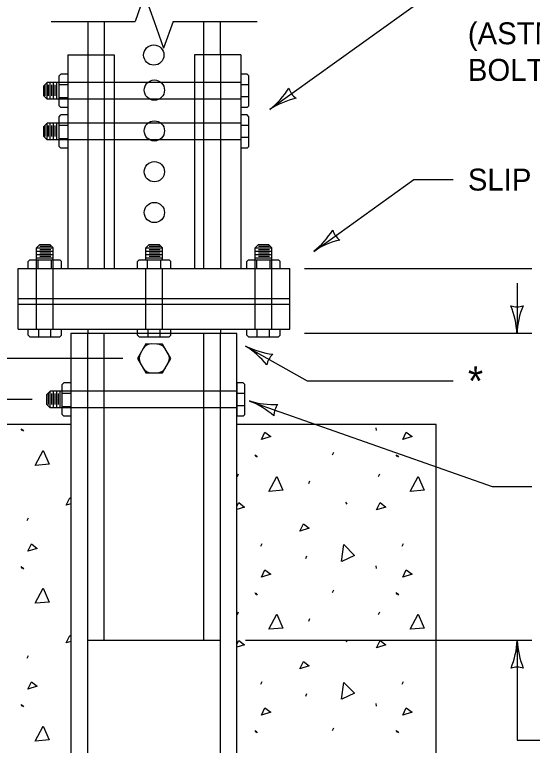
# Model space of a CAD drawing. Extents: x 49940 to 50043, y 49986 to 50011.
# Drawn here: x 50027.696 to 50029.113, y 49992.517 to 49994.515 of the extents above; entities that cross this region are included whole.
import ezdxf

# ---------------------------------------------------------------- set-up
doc = ezdxf.new("R2010")
doc.units = 0
for name, color, linetype in [('Level 1', 7, 'Continuous'), ('Level 2', 7, 'Continuous'), ('Level 3', 7, 'Continuous'), ('Level 4', 7, 'Continuous'), ('Level 6', 7, 'Continuous')]:
    doc.layers.add(name, color=color, linetype=linetype)

msp = doc.modelspace()

# ---------------------------------------------------------------- linework, layer by layer
at = {"layer": 'Level 1'}
for p, q in [((50027.8417, 49994.4053), (50027.8417, 49993.8208)), ((50027.8417, 49994.4053), (50027.9689, 49994.4053)), ((50027.9689, 49994.4053), (50027.9689, 49993.8208)), ((50028.1884, 49994.4053), (50028.1884, 49993.8208)), ((50028.3156, 49994.4053), (50028.1884, 49994.4053)), ((50028.3156, 49994.4053), (50028.3156, 49993.8208)), ((50027.8181, 49994.3475), (50027.8226, 49994.352)), ((50027.8181, 49994.2656), (50027.8181, 49994.3475)), ((50027.8417, 49994.352), (50027.8226, 49994.352)), ((50028.3323, 49994.352), (50028.3156, 49994.352)), ((50028.3368, 49994.3475), (50028.3323, 49994.352)), ((50028.3368, 49994.2656), (50028.3368, 49994.3475)), ((50027.7758, 49994.3202), (50027.7849, 49994.3293)), ((50027.8181, 49994.3293), (50027.7849, 49994.3293)), ((50027.7849, 49994.2839), (50027.7849, 49994.3293)), ((50027.7939, 49994.2839), (50027.7939, 49994.3293)), ((50027.8031, 49994.2839), (50027.8031, 49994.3293)), ((50027.8121, 49994.2839), (50027.8121, 49994.3293)), ((50027.7758, 49994.2931), (50027.7758, 49994.3202)), ((50027.7803, 49994.2932), (50027.7803, 49994.323)), ((50027.7894, 49994.2932), (50027.7894, 49994.323)), ((50027.7985, 49994.2932), (50027.7985, 49994.323)), ((50027.8076, 49994.2932), (50027.8076, 49994.323)), ((50027.8181, 49994.3241), (50027.8405, 49994.3241)), ((50028.3368, 49994.323), (50028.3162, 49994.323)), ((50027.7758, 49994.2931), (50027.7849, 49994.2839)), ((50027.8181, 49994.2879), (50027.8405, 49994.2879)), ((50028.3368, 49994.29), (50028.3162, 49994.29)), ((50027.8181, 49994.2839), (50027.7849, 49994.2839)), ((50027.8181, 49994.2656), (50027.8226, 49994.2612)), ((50027.8417, 49994.2612), (50027.8226, 49994.2612)), ((50028.3323, 49994.2612), (50028.3156, 49994.2612)), ((50028.3323, 49994.2612), (50028.3368, 49994.2656)), ((50027.8181, 49994.2359), (50027.8226, 49994.2405)), ((50027.8181, 49994.1541), (50027.8181, 49994.2359)), ((50027.8417, 49994.2405), (50027.8226, 49994.2405)), ((50028.3323, 49994.2405), (50028.3156, 49994.2405)), ((50028.3368, 49994.2359), (50028.3323, 49994.2405)), ((50028.3368, 49994.1541), (50028.3368, 49994.2359)), ((50027.7758, 49994.2087), (50027.7849, 49994.2178)), ((50027.7758, 49994.1816), (50027.7758, 49994.2087)), ((50027.7803, 49994.1816), (50027.7803, 49994.2115)), ((50027.8181, 49994.2178), (50027.7849, 49994.2178)), ((50027.7849, 49994.1723), (50027.7849, 49994.2178)), ((50027.7894, 49994.1816), (50027.7894, 49994.2115)), ((50027.7939, 49994.1723), (50027.7939, 49994.2178)), ((50027.7985, 49994.1816), (50027.7985, 49994.2115)), ((50027.8031, 49994.1723), (50027.8031, 49994.2178)), ((50027.8076, 49994.1816), (50027.8076, 49994.2115)), ((50027.8121, 49994.1723), (50027.8121, 49994.2178)), ((50027.8181, 49994.2126), (50027.8405, 49994.2126)), ((50028.3368, 49994.2115), (50028.3162, 49994.2115)), ((50027.7758, 49994.1816), (50027.7849, 49994.1723)), ((50027.8181, 49994.1723), (50027.7849, 49994.1723)), ((50027.8181, 49994.1763), (50027.8405, 49994.1763)), ((50028.3368, 49994.1785), (50028.3162, 49994.1785)), ((50027.8181, 49994.1541), (50027.8226, 49994.1496)), ((50027.8417, 49994.1496), (50027.8226, 49994.1496)), ((50028.3323, 49994.1496), (50028.3156, 49994.1496)), ((50028.3323, 49994.1496), (50028.3368, 49994.1541)), ((50027.7653, 49993.8865), (50027.7562, 49993.8775)), ((50027.7562, 49993.8443), (50027.7562, 49993.8775)), ((50027.7562, 49993.8775), (50027.8016, 49993.8775)), ((50027.7562, 49993.8685), (50027.8016, 49993.8685)), ((50027.7653, 49993.8865), (50027.7925, 49993.8865)), ((50027.7654, 49993.8821), (50027.7953, 49993.8821)), ((50027.7654, 49993.873), (50027.7953, 49993.873)), ((50027.7925, 49993.8865), (50027.8016, 49993.8775)), ((50027.8016, 49993.8443), (50027.8016, 49993.8775)), ((50028.0643, 49993.8865), (50028.0552, 49993.8775)), ((50028.0552, 49993.8443), (50028.0552, 49993.8775)), ((50028.0552, 49993.8775), (50028.1007, 49993.8775)), ((50028.0552, 49993.8685), (50028.1007, 49993.8685)), ((50028.0643, 49993.8865), (50028.0916, 49993.8865)), ((50028.0645, 49993.8821), (50028.0944, 49993.8821)), ((50028.0645, 49993.873), (50028.0944, 49993.873)), ((50028.0916, 49993.8865), (50028.1007, 49993.8775)), ((50028.1007, 49993.8443), (50028.1007, 49993.8775)), ((50028.3634, 49993.8865), (50028.3543, 49993.8775)), ((50028.3543, 49993.8443), (50028.3543, 49993.8775)), ((50028.3543, 49993.8775), (50028.3997, 49993.8775)), ((50028.3543, 49993.8685), (50028.3997, 49993.8685)), ((50028.3634, 49993.8865), (50028.3906, 49993.8865)), ((50028.3635, 49993.8821), (50028.3934, 49993.8821)), ((50028.3635, 49993.873), (50028.3934, 49993.873)), ((50028.3906, 49993.8865), (50028.3997, 49993.8775)), ((50028.3997, 49993.8443), (50028.3997, 49993.8775)), ((50027.7562, 49993.8593), (50027.8016, 49993.8593)), ((50027.7562, 49993.8503), (50027.8016, 49993.8503)), ((50027.7654, 49993.8639), (50027.7953, 49993.8639)), ((50027.7654, 49993.8548), (50027.7953, 49993.8548)), ((50028.0552, 49993.8593), (50028.1007, 49993.8593)), ((50028.0552, 49993.8503), (50028.1007, 49993.8503)), ((50028.0645, 49993.8639), (50028.0944, 49993.8639)), ((50028.0645, 49993.8548), (50028.0944, 49993.8548)), ((50028.3543, 49993.8593), (50028.3997, 49993.8593)), ((50028.3543, 49993.8503), (50028.3997, 49993.8503)), ((50028.3635, 49993.8639), (50028.3934, 49993.8639)), ((50028.3635, 49993.8548), (50028.3934, 49993.8548)), ((50027.7379, 49993.8443), (50027.7335, 49993.8397)), ((50027.7335, 49993.8208), (50027.7335, 49993.8397)), ((50027.7379, 49993.8443), (50027.8198, 49993.8443)), ((50027.7601, 49993.8443), (50027.7601, 49993.8219)), ((50027.7963, 49993.8443), (50027.7963, 49993.8219)), ((50027.8198, 49993.8443), (50027.8244, 49993.8397)), ((50027.8244, 49993.8208), (50027.8244, 49993.8397)), ((50028.037, 49993.8443), (50028.0324, 49993.8397)), ((50028.0324, 49993.8208), (50028.0324, 49993.8397)), ((50028.037, 49993.8443), (50028.1188, 49993.8443)), ((50028.0593, 49993.8443), (50028.0593, 49993.8219)), ((50028.0953, 49993.8443), (50028.0953, 49993.8219)), ((50028.1188, 49993.8443), (50028.1233, 49993.8397)), ((50028.1233, 49993.8208), (50028.1233, 49993.8397)), ((50028.3361, 49993.8443), (50028.3315, 49993.8397)), ((50028.3315, 49993.8208), (50028.3315, 49993.8397)), ((50028.3361, 49993.8443), (50028.4179, 49993.8443)), ((50028.3582, 49993.8443), (50028.3582, 49993.8219)), ((50028.3944, 49993.8443), (50028.3944, 49993.8219)), ((50028.4179, 49993.8443), (50028.4224, 49993.8397)), ((50028.4224, 49993.8208), (50028.4224, 49993.8397)), ((50027.7062, 49993.6548), (50027.7062, 49993.8208)), ((50027.7062, 49993.8208), (50028.0552, 49993.8208)), ((50028.0552, 49993.6548), (50028.0552, 49993.8208)), ((50028.0552, 49993.8208), (50028.1007, 49993.8208)), ((50028.1007, 49993.6548), (50028.1007, 49993.8208)), ((50028.1007, 49993.8208), (50028.4497, 49993.8208)), ((50028.4497, 49993.6548), (50028.4497, 49993.8208)), ((50027.7062, 49993.7383), (50028.4497, 49993.7383)), ((50027.7062, 49993.7234), (50028.4497, 49993.7234)), ((50027.7062, 49993.6548), (50028.0552, 49993.6548)), ((50027.7335, 49993.6381), (50027.7335, 49993.6548)), ((50027.7622, 49993.6337), (50027.7622, 49993.6543)), ((50027.7953, 49993.6337), (50027.7953, 49993.6543)), ((50027.8244, 49993.6381), (50027.8244, 49993.6548)), ((50027.8963, 49993.6548), (50027.8963, 49993.6425)), ((50028.0324, 49993.6381), (50028.0324, 49993.6548)), ((50028.0552, 49993.6548), (50028.1007, 49993.6548)), ((50028.0613, 49993.6337), (50028.0613, 49993.6543)), ((50028.0944, 49993.6337), (50028.0944, 49993.6543)), ((50028.1007, 49993.6548), (50028.4497, 49993.6548)), ((50028.1233, 49993.6381), (50028.1233, 49993.6548)), ((50028.2596, 49993.6548), (50028.2596, 49993.6425)), ((50028.3315, 49993.6381), (50028.3315, 49993.6548)), ((50028.3603, 49993.6337), (50028.3603, 49993.6543)), ((50028.3934, 49993.6337), (50028.3934, 49993.6543)), ((50028.4224, 49993.6381), (50028.4224, 49993.6548)), ((50027.7335, 49993.6381), (50027.7379, 49993.6337)), ((50027.7379, 49993.6337), (50027.8198, 49993.6337)), ((50027.8198, 49993.6337), (50027.8244, 49993.6381)), ((50028.0324, 49993.6381), (50028.037, 49993.6337)), ((50028.037, 49993.6337), (50028.1188, 49993.6337)), ((50028.1188, 49993.6337), (50028.1233, 49993.6381)), ((50028.3315, 49993.6381), (50028.3361, 49993.6337)), ((50028.3361, 49993.6337), (50028.4179, 49993.6337)), ((50028.4179, 49993.6337), (50028.4224, 49993.6381)), ((50027.8266, 49993.5031), (50027.8313, 49993.5077)), ((50027.8266, 49993.4213), (50027.8266, 49993.5031)), ((50027.8502, 49993.5077), (50027.8313, 49993.5077)), ((50028.3212, 49993.5077), (50028.3045, 49993.5077)), ((50028.3045, 49993.5077), (50028.3045, 49993.4167)), ((50028.3258, 49993.5031), (50028.3212, 49993.5077)), ((50028.3258, 49993.4213), (50028.3258, 49993.5031)), ((50027.7843, 49993.4759), (50027.7934, 49993.4849)), ((50027.7843, 49993.4485), (50027.7843, 49993.4759)), ((50027.7889, 49993.4488), (50027.7889, 49993.4786)), ((50027.8266, 49993.4849), (50027.7934, 49993.4849)), ((50027.7934, 49993.4395), (50027.7934, 49993.4849)), ((50027.7979, 49993.4488), (50027.7979, 49993.4786)), ((50027.8025, 49993.4395), (50027.8025, 49993.4849)), ((50027.8071, 49993.4488), (50027.8071, 49993.4786)), ((50027.8116, 49993.4395), (50027.8116, 49993.4849)), ((50027.8163, 49993.4488), (50027.8163, 49993.4786)), ((50027.8207, 49993.4395), (50027.8207, 49993.4849)), ((50027.8266, 49993.4797), (50027.8502, 49993.4797)), ((50028.3258, 49993.4786), (50028.3051, 49993.4786)), ((50027.7843, 49993.4485), (50027.7934, 49993.4395)), ((50027.8266, 49993.4395), (50027.7934, 49993.4395)), ((50027.8266, 49993.4434), (50027.8502, 49993.4434)), ((50028.3258, 49993.4455), (50028.3051, 49993.4455)), ((50027.8266, 49993.4213), (50027.8313, 49993.4167)), ((50027.8502, 49993.4167), (50027.8313, 49993.4167)), ((50028.3212, 49993.4167), (50028.3045, 49993.4167)), ((50028.3212, 49993.4167), (50028.3258, 49993.4213)), ((50027.8502, 49993.3945), (50027.3049, 49993.3945)), ((50028.8498, 49993.3945), (50028.3045, 49993.3945)), ((50028.8498, 49990.6682), (50028.8498, 49993.3945)), ((50027.7137, 49993.3824), (50027.7171, 49993.3775)), ((50027.7171, 49993.3805), (50027.7203, 49993.3755)), ((50028.6847, 49993.3847), (50028.6854, 49993.3775)), ((50028.3532, 49993.3115), (50028.3564, 49993.3065)), ((50028.3564, 49993.3097), (50028.3596, 49993.3047)), ((50028.5662, 49993.3115), (50028.5695, 49993.3187)), ((50028.7397, 49993.3115), (50028.7429, 49993.3065)), ((50028.7429, 49993.3097), (50028.7462, 49993.3047)), ((50028.3057, 49993.2516), (50028.3087, 49993.2589)), ((50028.692, 49993.2516), (50028.6953, 49993.2589)), ((50028.5009, 49993.2329), (50028.504, 49993.2403)), ((50028.6018, 49993.1814), (50028.6049, 49993.1765)), ((50027.7307, 49993.132), (50027.734, 49993.1393)), ((50028.3702, 49993.0611), (50028.3734, 49993.0684)), ((50028.7567, 49993.0611), (50028.76, 49993.0684)), ((50028.4928, 49993.028), (50028.4959, 49993.0352)), ((50027.7137, 49993.0054), (50027.7171, 49993.0004)), ((50027.7171, 49993.0036), (50027.7203, 49992.9987)), ((50028.6847, 49993.0078), (50028.6854, 49993.0004)), ((50028.3532, 49992.9343), (50028.3564, 49992.9296)), ((50028.3564, 49992.9325), (50028.3596, 49992.9277)), ((50028.5662, 49992.9343), (50028.5695, 49992.9418)), ((50028.7397, 49992.9343), (50028.7429, 49992.9296)), ((50028.7429, 49992.9325), (50028.7462, 49992.9277)), ((50028.3057, 49992.8746), (50028.3087, 49992.8819)), ((50028.692, 49992.8746), (50028.6953, 49992.8819)), ((50028.5009, 49992.8561), (50028.504, 49992.8633)), ((50028.6018, 49992.8044), (50028.6049, 49992.7995)), ((50027.7307, 49992.755), (50027.734, 49992.7623)), ((50028.3702, 49992.6841), (50028.3734, 49992.6914)), ((50028.7567, 49992.6841), (50028.76, 49992.6914)), ((50028.4928, 49992.6511), (50028.4959, 49992.6583)), ((50028.6847, 49992.631), (50028.6854, 49992.6236)), ((50027.7137, 49992.6283), (50027.7171, 49992.6236)), ((50027.7171, 49992.6265), (50027.7203, 49992.6218)), ((50028.3532, 49992.5575), (50028.3564, 49992.5526)), ((50028.3564, 49992.5556), (50028.3596, 49992.5508)), ((50028.5662, 49992.5575), (50028.5695, 49992.5647)), ((50028.7397, 49992.5575), (50028.7429, 49992.5526)), ((50028.7429, 49992.5556), (50028.7462, 49992.5508))]:
    msp.add_line(p, q, dxfattribs=at)
for points in [[(50027.8963, 49994.4966), (50027.8963, 49994.4053)], [(50028.2595, 49994.4053), (50028.2595, 49994.4966)], [(50028.3045, 49990.8092), (50028.3045, 49993.6425), (50027.8502, 49993.6425), (50027.8502, 49990.8092)], [(50028.3717, 49993.3533), (50028.3813, 49993.3735), (50028.3976, 49993.3613), (50028.3717, 49993.3533)], [(50028.7583, 49993.3533), (50028.768, 49993.3735), (50028.7841, 49993.3613), (50028.7583, 49993.3533)], [(50027.7525, 49993.2821), (50027.7744, 49993.3233), (50027.7912, 49993.2853), (50027.7533, 49993.2821)], [(50028.3919, 49993.2113), (50028.4137, 49993.2523), (50028.4306, 49993.2144), (50028.3926, 49993.2113)], [(50028.7785, 49993.2113), (50028.8003, 49993.2523), (50028.8172, 49993.2144), (50028.7793, 49993.2113)], [(50027.8375, 49993.1736), (50027.8471, 49993.1936), (50027.8502, 49993.1915)], [(50027.8502, 49993.1775), (50027.8375, 49993.1736)], [(50028.3045, 49993.1701), (50028.3095, 49993.1806), (50028.3257, 49993.1684), (50028.3045, 49993.1619)], [(50028.6865, 49993.1605), (50028.6961, 49993.1806), (50028.7123, 49993.1684), (50028.6865, 49993.1605)], [(50028.4768, 49993.1027), (50028.4865, 49993.1229), (50028.5026, 49993.1107), (50028.4768, 49993.1027)], [(50027.7324, 49993.0473), (50027.7422, 49993.0674), (50027.7581, 49993.0554), (50027.7324, 49993.0473)], [(50028.591, 49993.0197), (50028.5974, 49993.0657), (50028.6263, 49993.0361), (50028.5919, 49993.0199)], [(50028.3717, 49992.9764), (50028.3813, 49992.9966), (50028.3976, 49992.9844), (50028.3717, 49992.9764)], [(50028.7583, 49992.9764), (50028.768, 49992.9966), (50028.7841, 49992.9844), (50028.7583, 49992.9764)], [(50027.7525, 49992.9052), (50027.7744, 49992.9463), (50027.7912, 49992.9084), (50027.7533, 49992.9052)], [(50028.3919, 49992.8343), (50028.4137, 49992.8755), (50028.4306, 49992.8374), (50028.3926, 49992.8343)], [(50028.7785, 49992.8343), (50028.8003, 49992.8755), (50028.8172, 49992.8374), (50028.7793, 49992.8343)], [(50027.8375, 49992.7966), (50027.8471, 49992.8168), (50027.8502, 49992.8145)], [(50027.8502, 49992.8006), (50027.8375, 49992.7966)], [(50028.3045, 49992.7931), (50028.3095, 49992.8036), (50028.3257, 49992.7915), (50028.3045, 49992.7849)], [(50028.6865, 49992.7834), (50028.6961, 49992.8036), (50028.7123, 49992.7915), (50028.6865, 49992.7834)], [(50028.4768, 49992.7257), (50028.4865, 49992.746), (50028.5026, 49992.7338), (50028.4768, 49992.7257)], [(50027.7324, 49992.6703), (50027.7422, 49992.6905), (50027.7581, 49992.6784), (50027.7324, 49992.6703)], [(50028.591, 49992.6427), (50028.5974, 49992.6888), (50028.6263, 49992.659), (50028.5919, 49992.643)], [(50028.3717, 49992.5995), (50028.3813, 49992.6195), (50028.3976, 49992.6075), (50028.3717, 49992.5995)], [(50028.7583, 49992.5995), (50028.768, 49992.6195), (50028.7841, 49992.6075), (50028.7583, 49992.5995)], [(50027.7525, 49992.5283), (50027.7744, 49992.5694), (50027.7912, 49992.5314), (50027.7533, 49992.5283)]]:
    msp.add_lwpolyline(points, dxfattribs=at)
msp.add_lwpolyline([(50028.0324, 49993.5749), (50028.0552, 49993.5352), (50028.1008, 49993.535), (50028.124, 49993.5745), (50028.1012, 49993.6141), (50028.0556, 49993.6144)], close=True, dxfattribs=at)
for centre in [(50028.077, 49994.4045), (50028.0786, 49994.3085), (50028.0786, 49994.3085), (50028.0786, 49994.1969), (50028.0786, 49994.1969), (50028.0786, 49994.1969), (50028.0786, 49994.0854), (50028.0786, 49993.9738)]:
    msp.add_circle(centre, 0.0277, dxfattribs=at)
for centre, start, end in [((50028.0711, 49993.587), 89.696, 149.6971), ((50028.0853, 49993.5869), 29.6985, 89.6961), ((50028.064, 49993.5747), 149.6985, 209.6957), ((50028.0923, 49993.5746), 329.6973, 29.6966), ((50028.071, 49993.5624), 209.697, 269.6988), ((50028.0852, 49993.5623), 269.6962, 329.6979)]:
    msp.add_arc(centre, 0.0273, start, end, dxfattribs=at)
at = {"layer": 'Level 3'}
for p, q in [((50028.8246, 49994.5638), (50028.3946, 49994.2551)), ((50028.5147, 49993.8674), (50028.7882, 49994.0638)), ((50028.7882, 49994.0638), (50028.8964, 49994.0638)), ((50028.4897, 49993.8208), (50029.1111, 49993.8208)), ((50029.0711, 49993.7808), (50029.0711, 49993.6425)), ((50029.1111, 49993.6425), (50028.4897, 49993.6425)), ((50028.3277, 49993.6085), (50028.497, 49993.5136)), ((50027.9924, 49993.5749), (50026.9229, 49993.5749)), ((50028.497, 49993.5136), (50028.8964, 49993.5136)), ((50027.7443, 49993.4622), (50026.9229, 49993.4622)), ((50028.339, 49993.4583), (50029.0029, 49993.2248)), ((50029.0029, 49993.2248), (50029.1111, 49993.2248)), ((50028.3279, 49992.804), (50029.1111, 49992.804)), ((50029.0711, 49992.804), (50029.0711, 49992.5313)), ((50029.0711, 49992.5313), (50029.1793, 49992.5313))]:
    msp.add_line(p, q, dxfattribs=at)
for centre, radius, start, end in [((50028.2495, 49994.4378), 0.233, 308.5027, 327.7526), ((50028.4987, 49994.3302), 0.0548, 197.8142, 233.5366), ((50028.5167, 49994.0697), 0.2223, 103.1314, 123.3149), ((50028.3696, 49994.0501), 0.233, 308.5094, 327.7592), ((50028.6188, 49993.9425), 0.0548, 197.8209, 233.5433), ((50028.6368, 49993.682), 0.2223, 103.1381, 123.3216), ((50029.0708, 49993.7709), 0.0548, 252.1388, 287.8612), ((50028.8381, 49993.6312), 0.233, 2.8273, 22.0772), ((50029.2929, 49993.6335), 0.2223, 157.456, 177.6395), ((50028.2114, 49993.4194), 0.2223, 38.1835, 58.367), ((50028.4318, 49993.8173), 0.233, 243.5548, 262.8046), ((50028.4398, 49993.546), 0.0548, 132.8663, 168.5887), ((50028.2569, 49993.252), 0.2223, 48.0787, 68.2623), ((50028.4056, 49993.6818), 0.233, 253.45, 272.6999), ((50028.4602, 49993.416), 0.0548, 142.7616, 178.4839), ((50028.8492, 49992.813), 0.2223, 337.456, 357.6395), ((50029.3041, 49992.8153), 0.233, 182.8273, 202.0772), ((50029.0714, 49992.6756), 0.0548, 72.1388, 107.8612)]:
    msp.add_arc(centre, radius, start, end, dxfattribs=at)
at = {"layer": 'Level 4'}
for p, q in [((50028.3156, 49994.3293), (50027.8181, 49994.3293)), ((50028.3156, 49994.2839), (50027.8181, 49994.2839)), ((50028.3156, 49994.2178), (50027.8181, 49994.2178)), ((50028.3156, 49994.1723), (50027.8181, 49994.1723)), ((50027.7562, 49993.6548), (50027.7562, 49993.8443)), ((50027.8016, 49993.6548), (50027.8016, 49993.8443)), ((50028.3543, 49993.6548), (50028.3543, 49993.8443)), ((50028.3997, 49993.6548), (50028.3997, 49993.8443)), ((50027.8963, 49990.8092), (50027.8963, 49993.6425)), ((50027.9416, 49992.804), (50027.9416, 49993.6425)), ((50028.2141, 49992.804), (50028.2141, 49993.6425)), ((50028.2596, 49990.8092), (50028.2596, 49993.6425)), ((50028.3045, 49993.4849), (50027.8266, 49993.4849)), ((50028.3045, 49993.4395), (50027.8266, 49993.4395)), ((50027.8963, 49992.804), (50028.2596, 49992.804))]:
    msp.add_line(p, q, dxfattribs=at)
for points in [[(50027.9416, 49994.4966), (50027.9416, 49993.8208)], [(50028.2141, 49993.8208), (50028.2141, 49994.4966)], [(50027.8963, 49994.4053), (50027.8963, 49993.8208)], [(50028.2595, 49994.4053), (50028.2595, 49993.8208)]]:
    msp.add_lwpolyline(points, dxfattribs=at)
at = {"layer": 'Level 6'}
for p, q in [((50028.052, 49994.5697), (50028.0261, 49994.4966)), ((50028.052, 49994.5697), (50028.0779, 49994.4966)), ((50027.7963, 49994.4966), (50028.0261, 49994.4966)), ((50028.0779, 49994.4966), (50028.1038, 49994.4235)), ((50028.1297, 49994.4966), (50028.1038, 49994.4235)), ((50028.1297, 49994.4966), (50028.3595, 49994.4966))]:
    msp.add_line(p, q, dxfattribs=at)

# ---------------------------------------------------------------- texts
at = {"layer": 'Level 2'}
for s, p in [('(ASTM F 568M CLASS 4.6)', (50028.9364, 49994.4338)), ('BOLT AND NUT (2 REQURIED)', (50028.9364, 49994.3338)), ('SLIP BASE ASSEMBLY', (50028.9364, 49994.0338))]:
    msp.add_text(s, height=0.06, dxfattribs=at).set_placement(p)
msp.add_text('*', height=0.08, rotation=359.5, dxfattribs=at).set_placement((50028.9361, 49993.4736))

doc.saveas('drawing.dxf')
